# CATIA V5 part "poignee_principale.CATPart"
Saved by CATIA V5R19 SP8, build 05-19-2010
Part number: poignee_principale
Bounding box of the stored display mesh (mm): x -45 to 47, y -1590 to 127.28, z -54.631 to 55
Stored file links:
  U:\Thinkmotion\Assemblage final\poignee_principale.CATPart
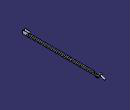
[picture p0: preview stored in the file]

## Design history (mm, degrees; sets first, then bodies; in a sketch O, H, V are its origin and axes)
Body1 (main body)
  Sketch1 on yz-plane, origin (0, 0, 0), H (0, 1, 0), V (0, 0, 1)
    circle A1 centre (0, 0) radius 20
  Pad1: profile Sketch1, direction (1, 0, 0), length 20, mirrored extent
  Sketch2 on end face of Pad1, origin (20, 0, 0), H (0, 1, 0), V (0, 0, 1)
    arc A1 centre (0, 0) radius 15 from (0, -15) to (-10, 11.1803) ccw
    line L1 (0, -15) -> (-10, -15)
    point P1 (0, -15)
    line L2 (-10, -15) -> (-10, 11.1803)
    length L2 = 26.1803
    coincidence: P1 V
    tangency: L1 A1
    vertical: L2 V
  Pad2: profile Sketch2, direction (1, 0, 0), length 25
  Mirror1: of Pad2, Sketch2, about yz-plane
  Sketch3 on zx-plane, origin (0, 0, 0), H (-1, 0, 0), V (0, 0, 1)
    circle A1 centre (0, 0) radius 15
  Sketch4 on yz-plane, origin (0, 0, 0), H (0, 1, 0), V (0, 0, 1)
    line L1 (0, 0) -> (30, 0)
    point P1 (30, 0)
    spline S1 through (30, 0) (100, -20) (120, -30)
    point P2 (30, 0)
    horizontal: L1 H
    coincidence: P2 P1
  Rib1: profile Sketch3, centre curve Sketch4
  Sketch5 on xy-plane, origin (0, 0, 0), H (1, 0, 0), V (0, 1, 0)
    line L1 (20, -10) -> (45, -10)
    line L2 (45, -10) -> (45, -50)
    line L3 (45, -50) -> (20, -50)
    line L4 (20, -50) -> (20, -10)
    reference projected line E1 (45, 15) -> (45, -15) from edge [face of Pad2 from Sketch2.A1 | end face of Pad2]
    reference projected line E2 (20, 20) -> (20, -20) from edge [face of Pad1 from Sketch1.A1 | end face of Pad1]
    reference projected line E3 through (0, 0) direction (1, 0) from axis of face of Pad2 from Sketch2.A1
    distance L1 E3 = 10
    horizontal: L1 H, L3 H
    vertical: L2 V, L4 V
    coincidence: L2 E1, L4 E2
  Pocket1: profile Sketch5, direction (0, 0, -1), length 25, mirrored extent
  Sketch6 on face of Pocket1, origin (0, -10, 0), H (1, 0, 0), V (0, 0, 1)
    line L1 (43, 11.1803) -> (45, 11.1803)
    line L2 (45, 11.1803) -> (45, -15)
    line L3 (45, -15) -> (43, -15)
    line L4 (43, -15) -> (43, 11.1803)
    reference projected line E1 (20, 11.1803) -> (45, 11.1803) from edge [face of Pocket1 | face of Pad2 from Sketch2.A1]
    reference projected line E2 (45, 11.1803) -> (45, -15) from edge [face of Pocket1 | end face of Pad2]
    reference projected line E3 (20, -15) -> (45, -15) from edge [face of Pad2 from Sketch2.L1 | face of Pocket1]
    length L1 = 2
    horizontal: L1 H, L3 H
    vertical: L2 V, L4 V
    coincidence: L1 E1, L2 E2, L3 E3
  Pad3: profile Sketch6, direction (0, -1, 0), length 1500
  Sketch7 on face of Pocket1, origin (20, 0, 0), H (0, 1, 0), V (0, 0, 1)
    line L1 (-8.0414, 11.1803) -> (-70.8462, 11.1803)
    line L2 (-73.3211, 10.1552) -> (-81.007, 2.4693)
    line L3 (-82.0321, -0.0055) -> (-82.0321, -31.2035)
    line L4 (-81.007, -33.6784) -> (-60.0543, -54.631)
    line L5 (-60.0543, -54.631) -> (-19.0892, -54.631)
    line L6 (-42.0321, -28.0719) -> (-42.0321, -9.5925)
    line L7 (-42.0321, -9.5925) -> (-8.0414, -9.5925)
    line L8 (-8.0414, -9.5925) -> (-8.0414, 11.1803)
    reference projected line E1 (-10, 11.1803) -> (-1010, 11.1803) from edge [face of Pad3 from Sketch6.L1 | face of Pad3]
    arc A1 centre (-19.0892, -39.631) radius 15 from (-19.0892, -54.631) to (-5.4216, -45.8114) ccw
    line L9 (-5.4216, -45.8114) -> (-2.4304, -39.1965)
    arc A2 centre (-7.8975, -36.7243) radius 6 from (-2.4304, -39.1965) to (-13.3645, -34.2522) ccw
    arc A3 centre (-27.0321, -28.0719) radius 15 from (-42.0321, -28.0719) to (-13.3645, -34.2522) ccw
    arc A4 centre (-78.5321, -31.2035) radius 3.5 from (-82.0321, -31.2035) to (-81.007, -33.6784) ccw
    arc A5 centre (-70.8462, 7.6803) radius 3.5 from (-70.8462, 11.1803) to (-73.3211, 10.1552) ccw
    arc A6 centre (-78.5321, -0.0055) radius 3.5 from (-81.007, 2.4693) to (-82.0321, -0.0055) ccw
    angle L2 L1 = 45
    angle L4 L5 = 45
    radius A4 = 3.5
    radius A5 = 3.5
    distance L6 L3 = 40
    radius A2 = 6
    horizontal: L1 H, L5 H, L7 H
    vertical: L3 V, L6 V, L8 V
    coincidence: L1 E1
    tangency: A1 L5, L9 A1, A2 L9, A3 L6, A3 A2, A4 L4, A4 L3, A5 L2, A5 L1, A6 L2, A6 L3
  Pad4: profile Sketch7, direction (1, 0, 0), length 2
  Sketch8 on face of Pad3 from Sketch6.L4, origin (43, 0, 0), H (0, -1, 0), V (0, 0, 1)
    line L1 (110, -13) -> (1510, -13)
    line L2 (1510, -13) -> (1510, -15)
    line L3 (1510, -15) -> (110, -15)
    line L4 (110, -15) -> (110, -13)
    reference projected line E1 (1510, 11.1803) -> (1510, -15) from edge [face of Pad3 from Sketch6.L4 | end face of Pad3]
    reference projected line E2 (10, -15) -> (1010, -15) from edge [face of Pad3 | face of Pad3 from Sketch6.L4]
    length L3 = 1400
    length L2 = 2
    horizontal: L1 H, L3 H
    vertical: L2 V, L4 V
    coincidence: L2 E1, L3 E2
  Pad5: profile Sketch8, direction (-1, 0, 0), length 50
  Sketch9 on face of Pad5 from Sketch8.L1, origin (0, 0, -13), H (1, 0, 0), V (0, 1, 0)
    line L1 (-7, -110) -> (-5, -110)
    line L2 (-5, -110) -> (-5, -1510)
    line L3 (-5, -1510) -> (-7, -1510)
    line L4 (-7, -1510) -> (-7, -110)
    reference projected line E1 (-7, -1010) -> (-7, -260) from edge [face of Pad5 from Sketch8.L1 | end face of Pad5]
    reference projected line E2 (43, -1510) -> (-7, -1510) from edge [face of Pad5 from Sketch8.L1 | face of Pad5]
    reference projected line E3 (43, -110) -> (-7, -110) from edge [face of Pad5 from Sketch8.L4 | face of Pad5 from Sketch8.L1]
    length L1 = 2
    horizontal: L1 H, L3 H
    vertical: L2 V, L4 V
    coincidence: L4 E1, L3 E2, L1 E3
  Pad6: profile Sketch9, direction (0, 0, 1), length 24.18
  Sketch10 on face of Pad5 from Sketch8.L1, origin (0, 0, -13), H (1, 0, 0), V (0, 1, 0)
    line L1 (19, -160) -> (23, -160)
    line L2 (23, -160) -> (23, -1460)
    line L3 (23, -1460) -> (19, -1460)
    line L4 (19, -1460) -> (19, -160)
    reference projected line E1 (-5, -1010) -> (-5, -260) from edge [face of Pad6 from Sketch9.L2 | end face of Pad6]
    reference projected line E2 (43, -10) -> (43, -1010) from edge [face of Pad3 from Sketch6.L4 | face of Pad3 from Sketch6.L1]
    reference projected line E3 (43, -1510) -> (-7, -1510) from edge [face of Pad5 from Sketch8.L1 | face of Pad6]
    length L1 = 4
    length L4 = 1300
    distance L3 E3 = 50
    horizontal: L1 H, L3 H
    vertical: L2 V, L4 V
    symmetry: E1 E2 L4
  Pocket2: profile Sketch10, direction (0, 0, -1), through (limit type 3)
  Sketch11 on face of Pad3, origin (45, 0, 0), H (0, 1, 0), V (0, 0, 1)
    point P1 (-1590, 55)
    line L1 (-1590, 55) -> (-1470, 55)
    line L2 (-1470, 55) -> (-1470, -5)
    line L3 (-1480, -15) -> (-1580, -15)
    line L4 (-1590, -5) -> (-1590, 55)
    point P3 (-1590, -15)
    arc A1 centre (-1480, -5) radius 10 from (-1480, -15) to (-1470, -5) ccw
    arc A2 centre (-1580, -5) radius 10 from (-1590, -5) to (-1580, -15) ccw
    point P8 (-1480, -15)
    point P9 (-1470, -5)
    point P10 (-1480, -15)
    point P11 (-1470, -5)
    reference projected line E1 (-1510, -15) -> (-1510, 11.1803) from edge [face of Pad3 | face of Pad6]
    length L1 = 120
    radius A2 = 10
    radius A1 = 10
    radius A1 = 10 (reference)
    distance L4 = 60
    distance P3 P1 = 70
    distance L2 E1 = 40
    horizontal: L1 H, L3 H
    vertical: L2 V, L4 V
    coincidence: L3, A1 P8, A1 P9, L2 P11, L3 P10, P8 P10, P9 P11
    tangency: A1 L3, A1 L2, A2 L3, A2 L4
  Pad7: profile Sketch11, direction (1, 0, 0), length 2
  Sketch12 on face of Pad6, origin (-7, 0, 0), H (0, -1, 0), V (0, 0, 1)
    line L1 (1470, 55) -> (1590, 55)
    line L2 (1590, 55) -> (1590, -5)
    line L3 (1580, -15) -> (1480, -15)
    line L4 (1470, -5) -> (1470, 55)
    reference projected line E1 (950, 55) -> (1070, 55) from edge [start face of Pad7 | face of Pad7 from Sketch11.L1]
    reference projected line E2 (1590, 55) -> (1590, -5) from edge [start face of Pad7 | face of Pad7 from Sketch11.L4]
    reference projected line E3 (1470, -5) -> (1470, 55) from edge [start face of Pad7 | face of Pad7 from Sketch11.L2]
    reference projected line E4 (1060, -15) -> (960, -15) from edge [start face of Pad7 | face of Pad7]
    arc A1 centre (1580, -5) radius 10 from (1580, -15) to (1590, -5) ccw
    reference projected arc E5 centre (1580, -5) radius 10 from (1580, -15) to (1590, -5) ccw from edge [start face of Pad7 | face of Pad7 from Sketch11.A2]
    reference projected arc E6 centre (1580, -5) radius 10 from (1580, -15) to (1590, -5) ccw from edge [start face of Pad7 | face of Pad7 from Sketch11.A2]
    arc A2 centre (1480, -5) radius 10 from (1470, -5) to (1480, -15) ccw
    reference projected arc E7 centre (1480, -5) radius 10 from (1470, -5) to (1480, -15) ccw from edge [face of Pad3 | face of Pad7 from Sketch11.A1]
    reference projected arc E8 centre (1480, -5) radius 10 from (1470, -5) to (1480, -15) ccw from edge [face of Pad3 | face of Pad7 from Sketch11.A1]
    horizontal: L1 H, L3 H
    vertical: L2 V, L4 V
    coincidence: L1 E1, L2 E2, L4 E3, L3 E4, A1 E5, A2 E7
    concentricity: A1 E6, A2 E8
  Pad8: profile Sketch12, direction (-1, 0, 0), length 2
